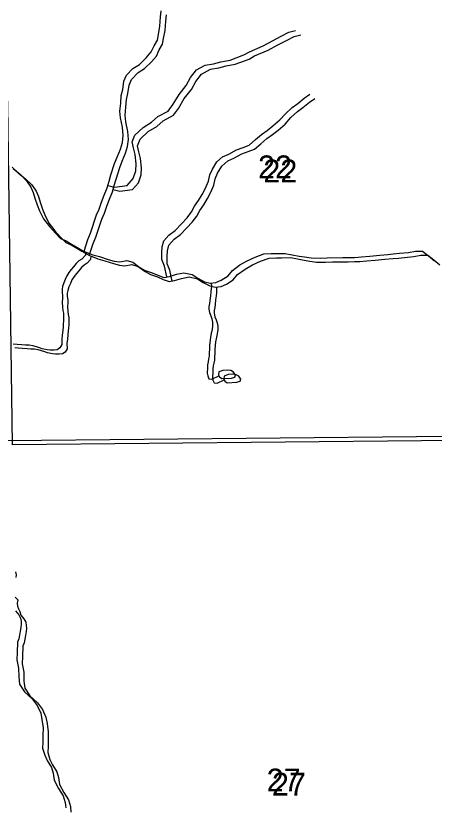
# Model space of a CAD drawing. Extents: x -21.1 to 50.3, y 0 to 22.1.
# Drawn here: x 47.215 to 47.981, y 14.98 to 16.437 of the extents above; entities that cross this region are included whole.
import ezdxf

# ---------------------------------------------------------------- set-up
doc = ezdxf.new("R2010")
doc.units = 0
for name, color, linetype in [('GM_X_Major_River', 7, 'Continuous'), ('GM_X_Minor_Lake', 7, 'Continuous'), ('GM_X_Minor_River', 7, 'Continuous'), ('GM_X_Section', 7, 'Continuous'), ('GM_X_Section_Text', 7, 'Continuous')]:
    doc.layers.add(name, color=color, linetype=linetype)

msp = doc.modelspace()

# ---------------------------------------------------------------- linework, layer by layer
at = {"layer": 'GM_X_Major_River'}
for points in [[(47.2086, 16.1604), (47.2197, 16.1499), (47.2338, 16.1383), (47.2445, 16.1277), (47.2526, 16.116), (47.2565, 16.1062), (47.26, 16.096), (47.2639, 16.0835), (47.2681, 16.0729), (47.2754, 16.0578), (47.2866, 16.0438), (47.2973, 16.0317), (47.3068, 16.0223), (47.3167, 16.0179), (47.3267, 16.0119), (47.3362, 16.0063), (47.3488, 15.9991), (47.3655, 15.9921), (47.3781, 15.9888), (47.3937, 15.9839), (47.4051, 15.9806), (47.415, 15.9796), (47.4278, 15.9819), (47.4392, 15.9786), (47.4518, 15.9692), (47.4614, 15.9636), (47.4747, 15.9595), (47.485, 15.9547), (47.4956, 15.9506), (47.5059, 15.9526), (47.5187, 15.9565), (47.5324, 15.9592), (47.5476, 15.9559), (47.5579, 15.9492), (47.5701, 15.9428), (47.5803, 15.9403), (47.5909, 15.9415), (47.6008, 15.9457), (47.6132, 15.9538), (47.6211, 15.9637), (47.6347, 15.9737), (47.6483, 15.9814), (47.6627, 15.988), (47.6789, 15.9938), (47.6922, 15.9943), (47.7017, 15.9943), (47.718, 15.9945), (47.7306, 15.9923), (47.7431, 15.9897)], [(47.2101, 16.1574), (47.2242, 16.1458), (47.2349, 16.1352), (47.243, 16.1235), (47.2468, 16.1137), (47.2503, 16.1035), (47.2542, 16.091), (47.2585, 16.0804), (47.2658, 16.0653), (47.2769, 16.0513), (47.2877, 16.0392), (47.2972, 16.0298), (47.3071, 16.0254), (47.317, 16.0194), (47.3266, 16.0138), (47.3391, 16.0066), (47.3559, 15.9996), (47.3684, 15.9963), (47.384, 15.9914), (47.3954, 15.9881), (47.4053, 15.9871), (47.4182, 15.9894), (47.4296, 15.9861), (47.4422, 15.9767), (47.4517, 15.9711), (47.465, 15.967), (47.4753, 15.9622), (47.486, 15.9581), (47.4962, 15.9601), (47.5091, 15.964), (47.5227, 15.9667), (47.5379, 15.9634), (47.5482, 15.9567), (47.5604, 15.9503), (47.5707, 15.9478), (47.5813, 15.949), (47.5911, 15.9532), (47.6036, 15.9613), (47.6115, 15.9712), (47.6251, 15.9812), (47.6387, 15.9889), (47.653, 15.9955), (47.6693, 16.0013), (47.6826, 16.0018), (47.6921, 16.0018), (47.7084, 16.002), (47.7209, 15.9998), (47.7335, 15.9972)], [(47.7335, 15.9972), (47.7433, 15.9958), (47.7559, 15.994), (47.7722, 15.9938), (47.7851, 15.9942), (47.8135, 15.9945), (47.8253, 15.9949), (47.8352, 15.995), (47.8477, 15.9962), (47.8632, 15.9971), (47.8811, 15.9992), (47.8958, 16.0004), (47.9057, 16.0012), (47.9171, 16.0025), (47.9338, 16.0041), (47.9466, 16.0065), (47.9595, 16.0066), (47.9706, 15.998), (47.9813, 15.9886)], [(47.7431, 15.9897), (47.753, 15.9883), (47.7655, 15.9865), (47.7818, 15.9863), (47.7947, 15.9867), (47.8232, 15.987), (47.8349, 15.9874), (47.8448, 15.9875), (47.8573, 15.9887), (47.8729, 15.9896), (47.8907, 15.9917), (47.9055, 15.9929), (47.9153, 15.9937), (47.9267, 15.995), (47.9434, 15.9966), (47.9563, 15.999), (47.9692, 15.9991), (47.9803, 15.9905), (47.9909, 15.9811)]]:
    msp.add_lwpolyline(points, dxfattribs=at)
at = {"layer": 'GM_X_Minor_Lake'}
for points in [[(47.6099, 15.774), (47.616, 15.776), (47.6171, 15.7794), (47.6136, 15.7851), (47.6086, 15.7877), (47.6022, 15.7888), (47.5942, 15.7879), (47.5867, 15.7852), (47.5863, 15.7799), (47.5879, 15.7761), (47.5925, 15.7731)], [(47.5925, 15.7731), (47.6099, 15.774)], [(47.6196, 15.7665), (47.6256, 15.7685), (47.6267, 15.7719), (47.6232, 15.7776), (47.6183, 15.7802), (47.6118, 15.7813), (47.6039, 15.7804), (47.5963, 15.7777), (47.596, 15.7724), (47.5975, 15.7686), (47.6021, 15.7656)], [(47.6021, 15.7656), (47.6196, 15.7665)]]:
    msp.add_lwpolyline(points, dxfattribs=at)
at = {"layer": 'GM_X_Minor_River'}
for points in [[(47.3401, 16.0062), (47.3469, 16.0278), (47.3521, 16.0392), (47.3555, 16.0502), (47.3592, 16.0616), (47.363, 16.0727), (47.3679, 16.0833), (47.3716, 16.0944), (47.3757, 16.1058), (47.3825, 16.1225), (47.3858, 16.1343), (47.3892, 16.1458), (47.3959, 16.1671), (47.4004, 16.1785), (47.4065, 16.193), (47.4102, 16.2055), (47.4116, 16.2181), (47.4104, 16.2332), (47.4069, 16.2507), (47.4057, 16.2625), (47.4071, 16.2773), (47.4082, 16.2914), (47.4108, 16.3024), (47.413, 16.3176), (47.4175, 16.3283), (47.4292, 16.3409), (47.4414, 16.3481), (47.4539, 16.3604), (47.4629, 16.371), (47.4682, 16.3825), (47.4742, 16.3928), (47.4761, 16.403), (47.479, 16.4179), (47.4801, 16.435), (47.4815, 16.4464)], [(47.3497, 15.9987), (47.3565, 16.0203), (47.3618, 16.0317), (47.3651, 16.0427), (47.3689, 16.0541), (47.3726, 16.0652), (47.3775, 16.0758), (47.3812, 16.0869), (47.3854, 16.0983), (47.3921, 16.115), (47.3955, 16.1268), (47.3988, 16.1383), (47.4056, 16.1596), (47.4101, 16.171), (47.4161, 16.1855), (47.4198, 16.198), (47.4213, 16.2106), (47.4201, 16.2257), (47.4165, 16.2432), (47.4153, 16.255), (47.4168, 16.2698), (47.4178, 16.2839), (47.4204, 16.2949), (47.4226, 16.3101), (47.4271, 16.3208), (47.4389, 16.3334), (47.451, 16.3406), (47.4635, 16.3529), (47.4726, 16.3635), (47.4778, 16.375), (47.4839, 16.3853), (47.4857, 16.3955), (47.4887, 16.4104), (47.4897, 16.4275), (47.4912, 16.4389)], [(47.3837, 16.1268), (47.3958, 16.1234), (47.419, 16.1265), (47.43, 16.1391), (47.4348, 16.1536), (47.4355, 16.1665), (47.4335, 16.1836), (47.4304, 16.1957), (47.4281, 16.2064), (47.433, 16.2186), (47.4481, 16.2327), (47.4637, 16.2423), (47.475, 16.2526), (47.494, 16.2626), (47.5031, 16.2752), (47.514, 16.2931), (47.5268, 16.3095), (47.5351, 16.3243), (47.5457, 16.3381), (47.5617, 16.3469), (47.5772, 16.3493), (47.5905, 16.3528), (47.6073, 16.3559), (47.6323, 16.3655), (47.6426, 16.3713), (47.6677, 16.382), (47.6851, 16.3913), (47.7007, 16.3997), (47.7151, 16.407), (47.7269, 16.4101)], [(47.3933, 16.1193), (47.4054, 16.1159), (47.4286, 16.119), (47.4396, 16.1316), (47.4445, 16.1461), (47.4452, 16.159), (47.4432, 16.1761), (47.4401, 16.1882), (47.4377, 16.1989), (47.4426, 16.2111), (47.4577, 16.2252), (47.4733, 16.2348), (47.4847, 16.2451), (47.5036, 16.2551), (47.5127, 16.2677), (47.5236, 16.2856), (47.5365, 16.302), (47.5448, 16.3168), (47.5553, 16.3306), (47.5713, 16.3394), (47.5869, 16.3418), (47.6002, 16.3453), (47.6169, 16.3484), (47.642, 16.358), (47.6522, 16.3638), (47.6773, 16.3745), (47.6947, 16.3838), (47.7103, 16.3922), (47.7247, 16.3995), (47.7365, 16.4026)], [(47.4916, 15.9592), (47.4876, 15.9792), (47.4826, 15.9909), (47.4825, 16.0038), (47.4828, 16.0145), (47.4858, 16.0251), (47.4953, 16.0358), (47.507, 16.0442), (47.5187, 16.0564), (47.5286, 16.0671), (47.5365, 16.0782), (47.5425, 16.0885), (47.5493, 16.0988), (47.5565, 16.1102), (47.5622, 16.1216), (47.5678, 16.1346), (47.5704, 16.146), (47.5749, 16.1567), (47.5828, 16.1696), (47.5934, 16.1792), (47.6048, 16.1842), (47.6192, 16.1918), (47.631, 16.1961), (47.642, 16.2003), (47.6541, 16.2106), (47.6648, 16.2202), (47.6754, 16.2275), (47.6856, 16.2355), (47.6985, 16.2466), (47.7091, 16.2584), (47.7208, 16.2695), (47.731, 16.2768), (47.7428, 16.2863), (47.753, 16.2936)], [(47.5012, 15.9517), (47.4972, 15.9717), (47.4922, 15.9834), (47.4921, 15.9963), (47.4925, 16.007), (47.4954, 16.0176), (47.5049, 16.0283), (47.5167, 16.0367), (47.5284, 16.0489), (47.5382, 16.0596), (47.5462, 16.0707), (47.5522, 16.081), (47.559, 16.0913), (47.5661, 16.1027), (47.5718, 16.1141), (47.5774, 16.1271), (47.58, 16.1385), (47.5845, 16.1492), (47.5925, 16.1621), (47.6031, 16.1717), (47.6144, 16.1767), (47.6289, 16.1843), (47.6406, 16.1886), (47.6517, 16.1928), (47.6638, 16.2031), (47.6744, 16.2127), (47.685, 16.22), (47.6952, 16.228), (47.7081, 16.2391), (47.7187, 16.2509), (47.7304, 16.262), (47.7407, 16.2693), (47.7524, 16.2788), (47.7627, 16.2861)], [(47.3431, 16.005), (47.3425, 15.9989), (47.336, 15.992), (47.3307, 15.9885), (47.3258, 15.984), (47.3209, 15.9779), (47.3167, 15.9729), (47.3122, 15.9672), (47.3084, 15.9611), (47.3058, 15.9546), (47.3028, 15.9485), (47.3005, 15.9417), (47.2998, 15.9367), (47.2998, 15.9314), (47.3006, 15.9249), (47.3006, 15.9196), (47.3003, 15.9128), (47.3007, 15.9037), (47.3015, 15.898), (47.3023, 15.8927), (47.3027, 15.8847), (47.3024, 15.8782), (47.3021, 15.8733), (47.3017, 15.868), (47.301, 15.8611), (47.3003, 15.8524), (47.2992, 15.8455), (47.2992, 15.8353), (47.2958, 15.8292), (47.2909, 15.8257), (47.2852, 15.8253), (47.278, 15.8253), (47.2726, 15.826), (47.2635, 15.8275), (47.2585, 15.8294), (47.2528, 15.8312), (47.2463, 15.8331), (47.2398, 15.8342), (47.233, 15.8345), (47.2265, 15.8349), (47.2178, 15.8356), (47.2101, 15.8363)], [(47.3527, 15.9975), (47.3521, 15.9914), (47.3457, 15.9845), (47.3403, 15.981), (47.3354, 15.9765), (47.3305, 15.9704), (47.3264, 15.9654), (47.3218, 15.9597), (47.318, 15.9536), (47.3154, 15.9471), (47.3124, 15.941), (47.3102, 15.9342), (47.3094, 15.9292), (47.3095, 15.9239), (47.3103, 15.9174), (47.3103, 15.9121), (47.3099, 15.9053), (47.3104, 15.8962), (47.3112, 15.8905), (47.312, 15.8852), (47.3124, 15.8772), (47.312, 15.8707), (47.3117, 15.8658), (47.3113, 15.8605), (47.3106, 15.8536), (47.3099, 15.8449), (47.3088, 15.838), (47.3089, 15.8278), (47.3055, 15.8217), (47.3005, 15.8182), (47.2948, 15.8178), (47.2876, 15.8178), (47.2823, 15.8185), (47.2731, 15.82), (47.2682, 15.8219), (47.2624, 15.8237), (47.256, 15.8256), (47.2495, 15.8267), (47.2426, 15.827), (47.2362, 15.8274), (47.2274, 15.8281), (47.2198, 15.8288), (47.2137, 15.8295)], [(47.5729, 15.948), (47.5731, 15.9424), (47.5727, 15.9375), (47.572, 15.9318), (47.5712, 15.9249), (47.5705, 15.9162), (47.5698, 15.9108), (47.5687, 15.9051), (47.5687, 15.9002), (47.5695, 15.8938), (47.5722, 15.8881), (47.5738, 15.8824), (47.5749, 15.8767), (47.575, 15.8702), (47.5743, 15.8626), (47.5728, 15.8565), (47.5713, 15.8482), (47.5699, 15.8345), (47.5695, 15.8269), (47.5692, 15.8204), (47.5688, 15.8144), (47.5677, 15.809), (47.567, 15.8041), (47.5659, 15.7984), (47.5659, 15.7927), (47.5656, 15.7828), (47.5664, 15.7779), (47.5683, 15.7729), (47.574, 15.7722), (47.587, 15.7782)], [(47.5826, 15.9405), (47.5827, 15.9349), (47.5823, 15.93), (47.5816, 15.9243), (47.5809, 15.9174), (47.5802, 15.9087), (47.5794, 15.9033), (47.5783, 15.8976), (47.5784, 15.8927), (47.5792, 15.8863), (47.5819, 15.8806), (47.5834, 15.8749), (47.5846, 15.8692), (47.5846, 15.8627), (47.5839, 15.8551), (47.5824, 15.849), (47.5809, 15.8407), (47.5795, 15.827), (47.5792, 15.8194), (47.5788, 15.8129), (47.5785, 15.8069), (47.5773, 15.8015), (47.5766, 15.7966), (47.5755, 15.7909), (47.5755, 15.7852), (47.5752, 15.7753), (47.576, 15.7704), (47.5779, 15.7654), (47.5836, 15.7647), (47.5967, 15.7707)], [(47.2148, 15.4193), (47.216, 15.414), (47.2153, 15.409)], [(47.2143, 15.3733), (47.2189, 15.368), (47.2178, 15.3619), (47.2182, 15.3566), (47.2202, 15.3517), (47.2225, 15.3468), (47.2244, 15.3403), (47.2302, 15.3335), (47.2333, 15.3271), (47.2344, 15.3214), (47.2345, 15.3161), (47.2341, 15.31), (47.233, 15.3031), (47.2315, 15.2959), (47.2304, 15.2894), (47.2278, 15.2834), (47.2273, 15.2644)], [(47.2148, 15.3478), (47.2205, 15.341), (47.2236, 15.3346), (47.2248, 15.3289), (47.2248, 15.3236), (47.2245, 15.3175), (47.2234, 15.3106), (47.2219, 15.3034), (47.2208, 15.2969), (47.2182, 15.2909), (47.2177, 15.2719)], [(47.2177, 15.2719), (47.2174, 15.2585), (47.2201, 15.243), (47.2206, 15.2271), (47.2218, 15.2138), (47.2314, 15.1998), (47.2451, 15.187), (47.2546, 15.175), (47.2608, 15.1606), (47.2631, 15.1492), (47.2651, 15.1341), (47.2648, 15.1196), (47.2645, 15.1075), (47.2642, 15.0965), (47.2681, 15.0836), (47.2727, 15.0738), (47.2803, 15.061), (47.2834, 15.0507), (47.2854, 15.0379), (47.2934, 15.0231), (47.3019, 15.0095), (47.3057, 14.9974), (47.3065, 14.9872)], [(47.2273, 15.2644), (47.227, 15.251), (47.2297, 15.2355), (47.2302, 15.2196), (47.2315, 15.2063), (47.241, 15.1923), (47.2547, 15.1795), (47.2642, 15.1675), (47.2704, 15.1531), (47.2727, 15.1417), (47.2747, 15.1266), (47.2744, 15.1121), (47.2742, 15.1), (47.2738, 15.089), (47.2777, 15.0761), (47.2823, 15.0663), (47.29, 15.0535), (47.2931, 15.0432), (47.295, 15.0304), (47.3031, 15.0156), (47.3115, 15.002), (47.3154, 14.9899), (47.3162, 14.9797)]]:
    msp.add_lwpolyline(points, dxfattribs=at)
at = {"layer": 'GM_X_Section'}
for points in [[(47.1739, 16.679), (48.1855, 16.6839), (48.1977, 15.669), (47.1998, 15.6592), (47.1908, 16.2808)], [(47.1836, 16.6715), (48.1952, 16.6764), (48.2073, 15.6615), (47.2094, 15.6517), (47.2004, 16.2733)]]:
    msp.add_lwpolyline(points, close=True, dxfattribs=at)

# ---------------------------------------------------------------- texts
at = {"layer": 'GM_X_Section_Text'}
for s, p in [('22', (47.6584, 16.1397)), ('22', (47.6681, 16.1322)), ('27', (47.6742, 15.0174)), ('27', (47.6839, 15.0099))]:
    msp.add_text(s, height=0.04186, rotation=0, dxfattribs=at).set_placement(p)

doc.saveas('drawing.dxf')
